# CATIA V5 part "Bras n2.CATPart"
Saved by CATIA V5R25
Part number: Part9
Bounding box of the stored display mesh (mm): x -145 to 0, y -7.5 to 7.5, z 0 to 10
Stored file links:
  C:\Users\m000605\Desktop\Projet FAB liseuse\Bras n2.CATPart
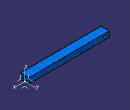
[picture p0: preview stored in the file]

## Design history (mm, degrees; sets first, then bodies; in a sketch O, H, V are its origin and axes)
AxisSystem1: origin (0, 0, 0), X (1, 0, 0), Y (0, 1, 0), Z (0, 0, 1)
Set1
  Sketch1 on XY plane of AxisSystem1, origin (0, 0, 0), H (1, 0, 0), V (0, 1, 0)
    line L1 (-145, 7.5) -> (145, 7.5)
    line L2 (145, 7.5) -> (145, -7.5)
    line L3 (145, -7.5) -> (-145, -7.5)
    line L4 (-145, -7.5) -> (-145, 7.5)
    length L1 = 290
    length L2 = 15
    horizontal: L1 H, L3 H
    vertical: L2 V, L4 V
    symmetry: L3 L1 H, L2 L4 V
Body1 (main body)
  Pad1: profile Sketch1, direction (0, 0, 1), length 10
  Sketch2 on face of Pad1 from Sketch1.L1, origin (0, 7.5, 0), H (-1, 0, 0), V (0, 0, 1)
    circle A1 centre (137.45, 5) radius 2.55
    point P1 (137.45, 5)
    reference projected line E1 (145, 0) -> (145, 10) from edge [face of Pad1 from Sketch1.L4 | face of Pad1 from Sketch1.L1]
    reference projected line E2 (-145, 0) -> (145, 0) from edge [start face of Pad1 | face of Pad1 from Sketch1.L1]
    radius A1 = 2.55
    distance A1 E1 = 5
    distance P1 E2 = 5
  Pocket1: profile Sketch2, direction (0, -1, 0), through (limit type 6)
  Sketch3 on ZX plane of AxisSystem1, origin (0, 0, 0), H (0, 0, 1), V (1, 0, 0)
    point P1 (0, 145)
    line L1 (0, 145) -> (10, 145)
    point P2 (10, 145)
    reference projected point E1 (10, 145) from vertex [face of Pad1 from Sketch1.L1 | end face of Pad1 | face of Pad1 from Sketch1.L2]
    line L2 (10, 145) -> (0, 139)
    point P3 (0, 139)
    line L3 (0, 139) -> (0, 145)
    length L1 = 10
    length L3 = 6
    coincidence: P1 V, P2 E1, P3 V
    vertical: L3 V
  Pocket2: profile Sketch3, direction (0, -1, 0), through (limit type 6), offset 6, opposite side length 8
  Sketch4 on face of Pocket2 from Sketch3.L2, origin (102.2059, 0, -61.3235), H (0, 1, 0), V (0.5145, 0, 0.8575)
    line L1 (12.5, 86.5149) -> (12.5, 71.5149)
    line L2 (12.5, 71.5149) -> (-12.5, 71.5149)
    line L3 (-12.5, 71.5149) -> (-12.5, 86.5149)
    reference projected line E1 (-7.5, 71.5149) -> (7.5, 71.5149) from edge [start face of Pad1 | face of Pocket2 from Sketch3.L2]
    line L4 (-12.5, 86.5149) -> (-7.5, 86.5149)
    point P5 (-7.5, 86.5149)
    line L5 (12.5, 86.5149) -> (7.5, 86.5149)
    line L6 (7.5, 86.5149) -> (7.5, 83.1768)
    line L7 (7.5, 83.1768) -> (-7.5, 83.1768)
    line L8 (-7.5, 83.1768) -> (-7.5, 86.5149)
    point P9 (-7.5, 86.5149)
    reference projected line E2 (7.5, 83.1768) -> (7.5, 71.5149) from edge [face of Pocket2 from Sketch3.L2 | face of Pad1 from Sketch1.L1]
    reference projected line E3 (-7.5, 83.1768) -> (-7.5, 71.5149) from edge [face of Pad1 from Sketch1.L3 | face of Pocket2 from Sketch3.L2]
    reference projected line E4 (-7.5, 83.1768) -> (7.5, 83.1768) from edge [face of Pocket2 from Sketch3.L2 | end face of Pad1]
    length L5 = 5
    length L3 = 15
    horizontal: L2 H, L4 H, L5 H, L7 H
    vertical: L1 V, L3 V, L6 V
    symmetry: L1 L3 V
    coincidence: L2 E1, L8 P5, E2 L6, E3 L8, L7 E4, P9 P5, L5 L4
  Pad2: profile Sketch4, direction (0.8575, 0, -0.5145), length 2
  Sketch5 on end face of Pad2, origin (103.9209, 0, -62.3525), H (0, 1, 0), V (0.5145, 0, 0.8575)
    line L1 (-7.5, 83.1768) -> (7.5, 83.1768)
    line L2 (7.5, 83.1768) -> (7.5, 78.1768)
    line L3 (7.5, 78.1768) -> (-7.5, 78.1768)
    line L4 (-7.5, 78.1768) -> (-7.5, 83.1768)
    reference projected line E1 (7.5, 86.5149) -> (7.5, 83.1768) from edge [face of Pad2 from Sketch4.L6 | end face of Pad2]
    reference projected line E2 (-7.5, 83.1768) -> (-7.5, 86.5149) from edge [face of Pad2 from Sketch4.L8 | end face of Pad2]
    reference projected line E3 (7.5, 83.1768) -> (-7.5, 83.1768) from edge [face of Pad2 from Sketch4.L7 | end face of Pad2]
    length L2 = 5
    horizontal: L1 H, L3 H
    vertical: L2 V, L4 V
    coincidence: L2 E1, L4 E2, E3 L1
  Pocket3: profile Sketch5, direction (-0.8575, 0, 0.5145), through (limit type 6)
  Split1: SplitPlane YZ plane of AxisSystem1
  Sketch6 on face of Split1, origin (0, 0, 0), H (0, 1, 0), V (0, 0, 1)
    line L1 (-3.5, 7.5) -> (3.5, 7.5)
    line L2 (3.5, 7.5) -> (3.5, 2.5)
    line L3 (3.5, 2.5) -> (-3.5, 2.5)
    line L4 (-3.5, 2.5) -> (-3.5, 7.5)
    reference projected line E1 (7.5, 0) -> (-7.5, 0) from edge [face of Split1 | start face of Pad1]
    length L1 = 7
    length L2 = 5
    distance E1 L3 = 2.5
    horizontal: L1 H, L3 H
    vertical: L2 V, L4 V
    symmetry: L2 L4 V
  Pocket4: profile Sketch6, direction (-1, 0, 0), length 11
